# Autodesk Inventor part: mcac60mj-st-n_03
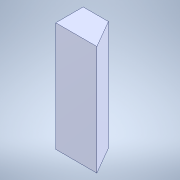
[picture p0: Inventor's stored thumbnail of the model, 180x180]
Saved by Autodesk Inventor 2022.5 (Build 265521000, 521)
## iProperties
Created: 2023-04
Part Number: mcac60mj-st-n_03
Material: Generic
Document SubType Name: Modeling
Designer: ImaoCorp
Density: 1 g/cm^3
Appearance: Default
Author: ImaoCorp
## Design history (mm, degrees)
feature "mcac60mj-st-n_03"
node "ソリッド1"
